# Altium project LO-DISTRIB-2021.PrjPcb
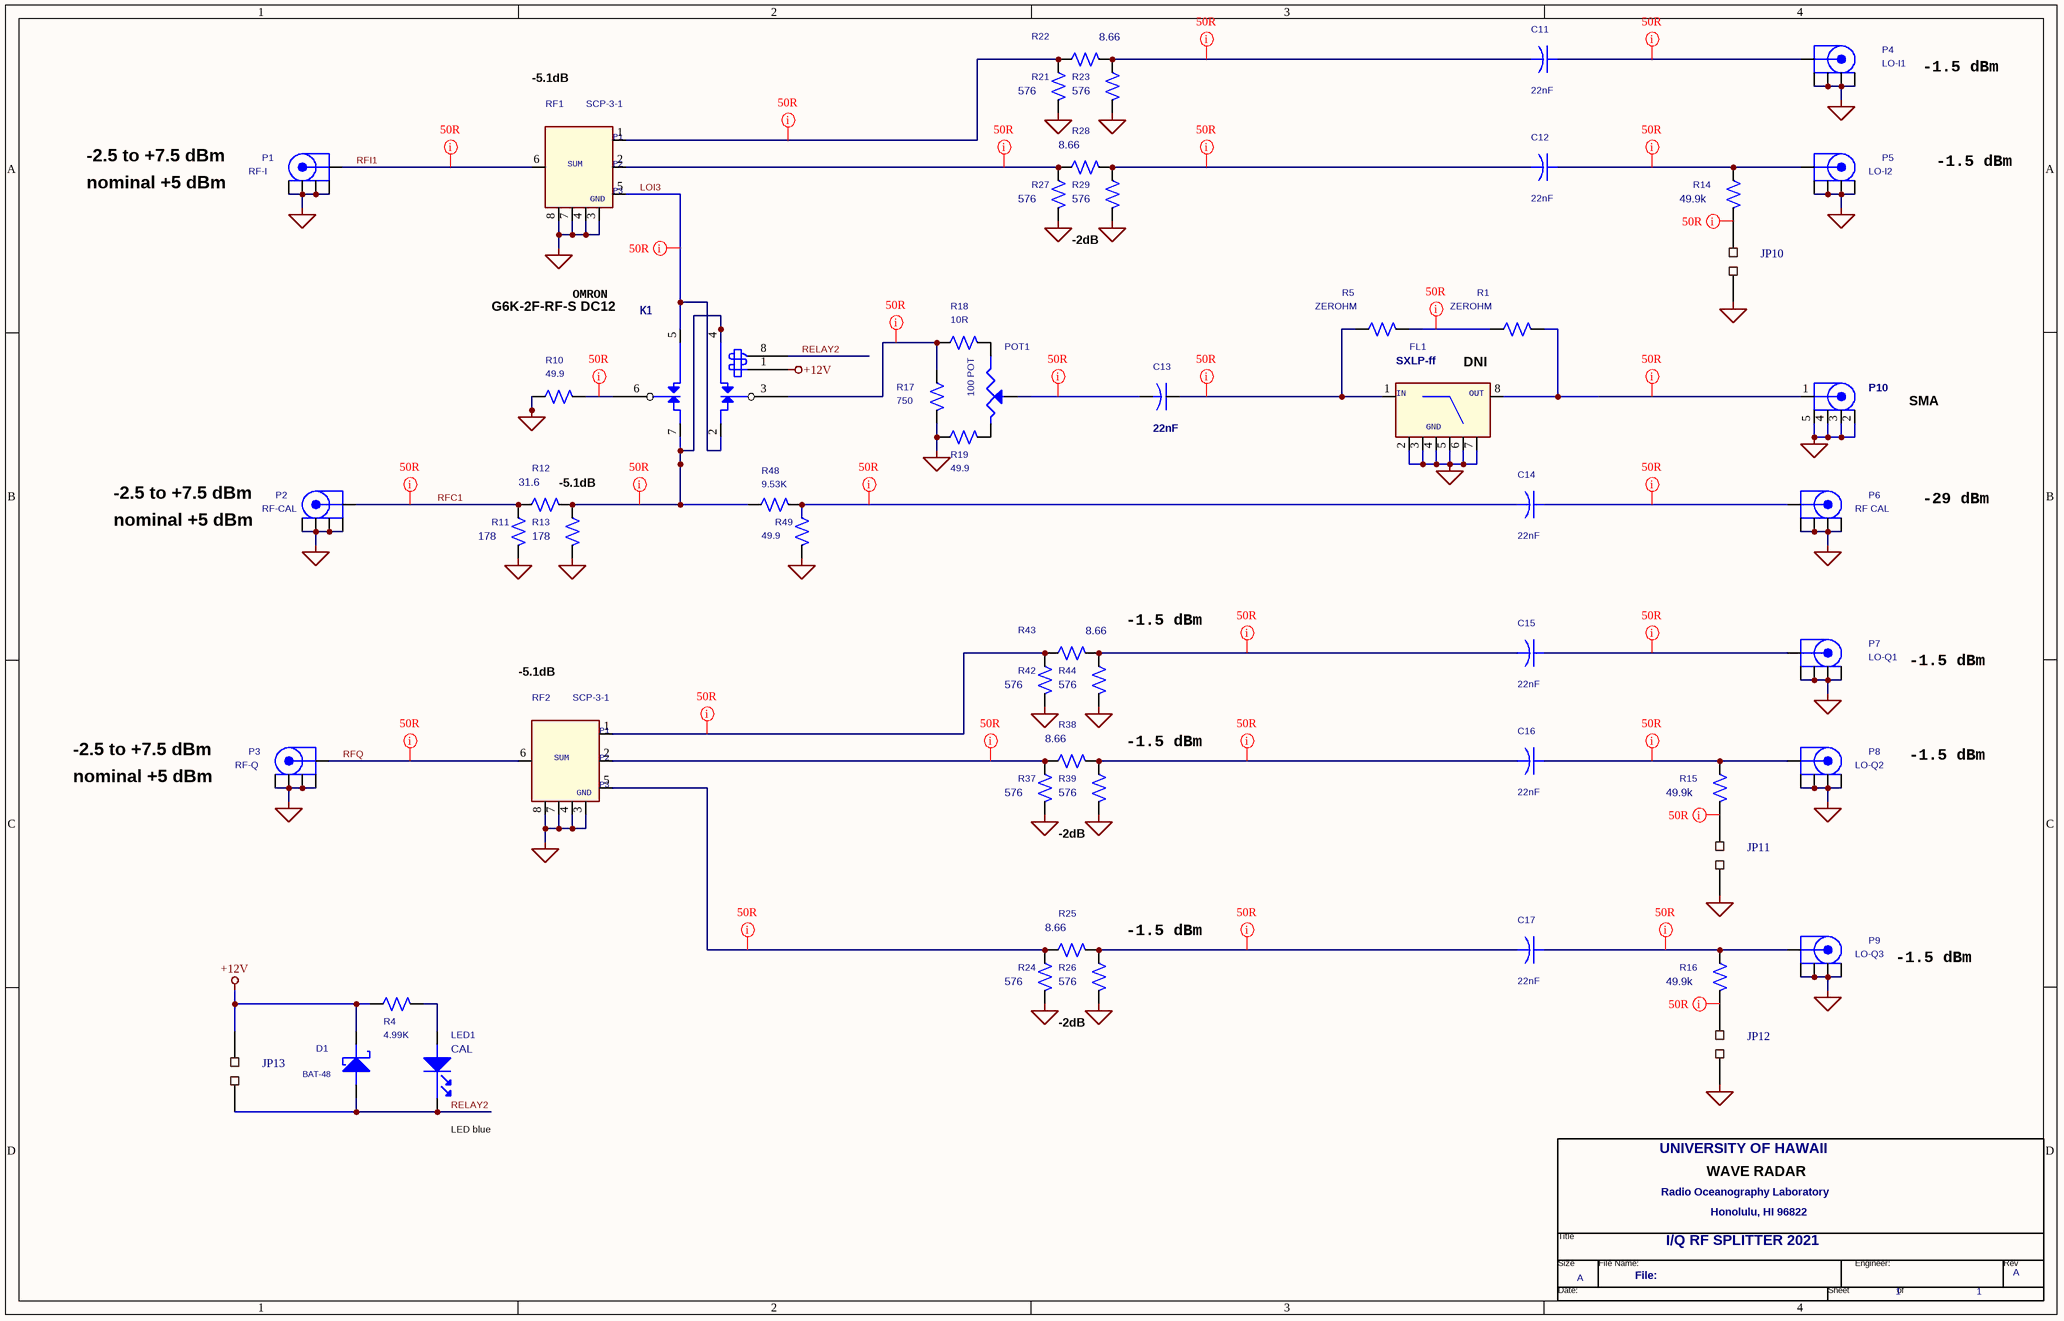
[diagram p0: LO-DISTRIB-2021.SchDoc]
1 sheet, 59 parts. Net scope: global (net labels, ports and power ports of the same name join across sheets).
Board file: LO-DISTRIB-2021.PcbDoc

## Sheet LO-DISTRIB-2021.SchDoc
size 386 x 246 mm; Organization: Altium Limited; Address1: L3, 12a Rodborough Rd; Address2: Frenchs Forest; Address3: NSW; Address4: Australia 2086

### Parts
*  Page Count: 1  Page Size: A  OrgAddr3: Honolulu, HI 96822  OrgAddr1: Radio Oceanography Laboratory  OrgName: UNIVERSITY OF HAWAII  Title: I/Q RF SPLITTER 2021  Doc: File:  (hidden comment: HWRadar)  (graphical)
C11  22nF  [1206]
C12  22nF  [1206]
C13  22nF  [1206]
C14  22nF  [1206]
C15  22nF  [1206]
C16  22nF  [1206]
C17  22nF  [1206]
D1  BAT-48  [SOD123]
FL1  SXLP-ff  [HF1149]
JP10  (no value)  [2X2.54]
JP11  (no value)  [2X2.54]
JP12  (no value)  [2X2.54]
JP13  (no value)  [22112022]
K1  G6K-2F-RF-S DC12  [RELAY-RF]  (value not drawn)
LED1  CAL  [LED1206-BLEUE]
P1  RF-I  [MCX-J-P-H-ST-TH1]
P2  RF-CAL  [MCX-J-P-H-ST-TH1]
P3  RF-Q  [MCX-J-P-H-ST-TH1]
P4  LO-I1  [MCX-J-P-H-ST-TH1]
P5  LO-I2  [MCX-J-P-H-ST-TH1]
P6  RF CAL  [MCX-J-P-H-ST-TH1]
P7  LO-Q1  [MCX-J-P-H-ST-TH1]
P8  LO-Q2  [MCX-J-P-H-ST-TH1]
P9  LO-Q3  [MCX-J-P-H-ST-TH1]
P10  (no value)  [5-1814832-1]
POT1  100 POT  [3296W]
R1  ZEROHM  [1206]
R4  4.99K  [1206]
R5  ZEROHM  [1206]
R10  49.9  [1206]
R11  178  [1206]
R12  31.6  [1206]
R13  178  [1206]
R14  49.9k  [1206]
R15  49.9k  [1206]
R16  49.9k  [1206]
R17  750  [1206]
R18  10R  [1206]
R19  49.9  [1206]
R21  576  [1206]
R22  8.66  [1206]
R23  576  [1206]
R24  576  [1206]
R25  8.66  [1206]
R26  576  [1206]
R27  576  [1206]
R28  8.66  [1206]
R29  576  [1206]
R37  576  [1206]
R38  8.66  [1206]
R39  576  [1206]
R42  576  [1206]
R43  8.66  [1206]
R44  576  [1206]
R48  9.53K  [1206]
R49  49.9  [1206]
RF1  SCP-3-1  [SCP-3-1]
RF2  SCP-3-1  [SCP-3-1]

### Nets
+12V: D1.K(CATHODE) JP13.2 K1.1(COIL1) R4.1
GND: FL1.2(GND) FL1.3(GND) FL1.4(GND) FL1.5(GND) FL1.6(GND) FL1.7(GND) JP10.1 JP11.1 JP12.1 K1.10(GND) K1.11(GND) K1.12(GND) K1.13(GND) K1.14(GND) K1.15(GND) P1.2(SHIELD) P1.3(SHIELD) P1.4(SHIELD) P1.5(SHIELD) P2.2(SHIELD) P2.3(SHIELD) P2.4(SHIELD) P2.5(SHIELD) P3.2(SHIELD) P3.3(SHIELD) P3.4(SHIELD) P3.5(SHIELD) P4.2(SHIELD) P4.3(SHIELD) P4.4(SHIELD) P4.5(SHIELD) P5.2(SHIELD) P5.3(SHIELD) P5.4(SHIELD) P5.5(SHIELD) P6.2(SHIELD) P6.3(SHIELD) P6.4(SHIELD) P6.5(SHIELD) P7.2(SHIELD) P7.3(SHIELD) P7.4(SHIELD) P7.5(SHIELD) P8.2(SHIELD) P8.3(SHIELD) P8.4(SHIELD) P8.5(SHIELD) P9.2(SHIELD) P9.3(SHIELD) P9.4(SHIELD) P9.5(SHIELD) P10.2(SHIELD) P10.3(SHIELD) P10.4(SHIELD) P10.5(SHIELD) R10.1 R11.2 R13.2 R17.2 R19.1 R21.2 R23.2 R24.2 R26.2 R27.2 R29.2 R37.2 R39.2 R42.2 R44.2 R49.2 RF1.3(GND) RF1.4(GND) RF1.7(GND) RF1.8(GND) RF2.3(GND) RF2.4(GND) RF2.7(GND) RF2.8(GND)  [also labelled GND_SIGNAL]
LOI3: K1.2(NC1) K1.5(NO2) RF1.5(P3)
RELAY2: D1.A(ANODE) JP13.1 K1.8(COIL2) LED1.K(CATHODE)
RFC1: P2.1(CENTER) R11.1 R12.1
RFI1: P1.1(CENTER) RF1.6(SUM)
RFQ: P3.1(CENTER) RF2.6(SUM)
NetC11_1: C11.1 P4.1(CENTER)
NetC11_2: C11.2 R22.2 R23.1
NetC12_1: C12.1 P5.1(CENTER) R14.1
NetC12_2: C12.2 R28.2 R29.1
NetC13_1: C13.1 FL1.1(IN) R5.1
NetC13_2: C13.2 POT1.2(WIPER)
NetC14_1: C14.1 P6.1(CENTER)
NetC14_2: C14.2 R48.2 R49.1
NetC15_1: C15.1 P7.1(CENTER)
NetC15_2: C15.2 R43.2 R44.1
NetC16_1: C16.1 P8.1(CENTER) R15.1
NetC16_2: C16.2 R38.2 R39.1
NetC17_1: C17.1 P9.1(CENTER) R16.1
NetC17_2: C17.2 R25.2 R26.1
NetFL1_8: FL1.8(OUT) P10.1(CENTER) R1.2
NetJP10_2: JP10.2 R14.2
NetJP11_2: JP11.2 R15.2
NetJP12_2: JP12.2 R16.2
NetK1_3: K1.3(COMMON2) R17.1 R18.1
NetK1_4: K1.4(NO1) K1.7(NC2) R12.2 R13.1 R48.1
NetK1_6: K1.6(COMMON1) R10.2
NetLED1_A: LED1.A(ANODE) R4.2
NetPOT1_1: POT1.1(A) R19.2
NetPOT1_3: POT1.3(B) R18.2
NetR1_1: R1.1 R5.2
NetR21_1: R21.1 R22.1 RF1.1(P1)
NetR24_1: R24.1 R25.1 RF2.5(P3)
NetR27_1: R27.1 R28.1 RF1.2(P2)
NetR37_1: R37.1 R38.1 RF2.2(P2)
NetR42_1: R42.1 R43.1 RF2.1(P1)

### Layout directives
net class 50R: LOI3, NetC11_1, NetC11_2, NetC12_1, NetC12_2, NetC13_1, NetC13_2, NetC14_1, NetC14_2, NetC15_1, NetC15_2, NetC16_1, NetC16_2, NetC17_1, NetC17_2, NetFL1_8, NetJP10_2, NetJP11_2, NetJP12_2, NetK1_3, NetK1_4, NetK1_6, NetR1_1, NetR21_1, NetR24_1, NetR27_1, NetR37_1, NetR42_1, RFC1, RFI1, RFQ

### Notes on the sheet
- -5.1dB
- -1.5 dBm
- -2.5 to +7.5 dBm
- nominal +5 dBm
- -2dB
- G6K-2F-RF-S DC12
- OMRON
- DNI
- SMA
- (near P2) -2.5 to +7.5 dBm
- (near R12) -5.1dB
- -29 dBm
- (near LED1) LED blue

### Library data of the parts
* = HWRadar: OrgAddr2: 2525 Correa Road; Engineer:: <ENG>
C11 C12 C14-C17 = CAP1206: MFR: Murata; MFR PART: GRM3195C1H223JA01D; DK Stock: 490-1761-1-ND
C13 = CAP: MFR: Murata; MFR PART: GRM3195C1H223JA01D; DK Stock: 490-1761-1-ND
D1 = DIODE SCHOTTKY: MFR: STMicroelectronic; MFR PART: BAT48ZFILM; DK Stock: 497-5712-1-ND
FL1 = LP FILTER_1: MFR: MiniCircuits
JP10-JP13 = STRAP
K1 = RELAY DPDT_1: MFR: Omron; DK Stock: Z2831-ND
LED1 = LED_1: MFR: Kingbright; MFR PART: APTL3216QBC/D; DK Stock: 754-1445-1-ND
P1-P3 = MCX_PCB: MCX-J-P-H-ST-TH1; MFR: Molex; MFR PART: 733660061; DK Stock: WM5541-ND
P4-P9 = MCX_PCB: MFR: Molex; MFR PART: 733660061; DK Stock: WM5541-ND
P10 = SMA-4G: MFR: TE Connectivity AMP Connectors; DK Stock: A97594-ND
POT1 = POT: MFR: Bourns; MFR PART: 3296W-1-101LF; DK Stock: 3296W-101LF-ND
R1 R5 = RES1206: MFR PART: RC1206JR-070RL; MFR: Yageo; DK Stock: 311-0.0ERCT-ND
R4 = RES1206: MFR: Yageo; MFR PART: RC1206FR-071KL; DK Stock: 311-1.00KFRCT-ND
R10 R19 R48 R49 = RES1206: MFR: Yageo; MFR PART: RC1206FR-0749R9L; DK Stock: 311-49.9FRCT-ND
R11 R13 = RES: MFR: Yageo; MFR PART: RC1206FR-07178RL; DK Stock: 311-178FRCT-ND
R12 = RES: MFR: Yageo; MFR PART: RC1206FR-0730R1L; DK Stock: 311-30.1FRCT-ND
R14-R16 = RES: MFR: Yageo; MFR PART: RC1206FR-074K99L; DK Stock: 311-4.99KFRCT-ND
R17 = RES1206: MFR: Yageo; MFR PART: RC1206FR-07750RL; DK Stock: 311-750FRCT-ND
R18 = RES1206: MFR: Yageo; MFR PART: RC1206FR-0710RL; DK Stock: 311-10.0FRCT-ND
R21 R23 R24 R26 R27 R29 R37 R39 R42 R44 = RES: MFR: Yageo; MFR PART: RC1206FR-07432RL; DK Stock: 311-432FRCT-ND
R22 R25 R28 R38 R43 = RES: MFR: Yageo; MFR PART: RC1206FR-0711R5L; DK Stock: 311-11.5FRCT-ND
RF1 RF2 = SCP-3-1: MFR: MiniCircuits; MFR PART: SCP-3-1+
